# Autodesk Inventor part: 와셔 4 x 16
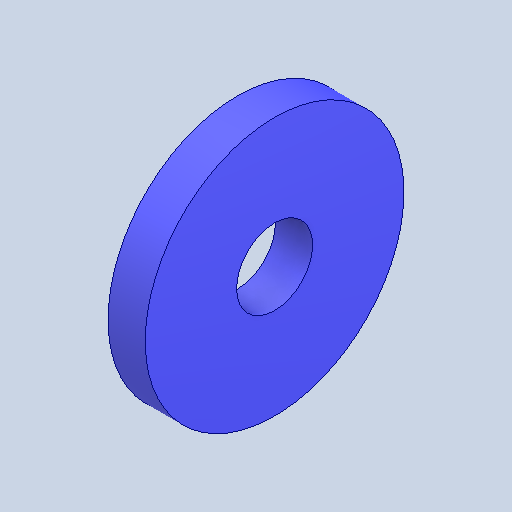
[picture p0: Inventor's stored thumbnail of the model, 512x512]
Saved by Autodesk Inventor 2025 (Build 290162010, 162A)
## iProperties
Created: 2024-07
Part Number: 와셔 4 x 16
Material: 강철, 연강
Description: 미터법 평면 와셔
Document SubType Name: Modeling
Designer: Admin
Density: 7.85 g/cm^3
Appearance: 기본값
Author: jhkim
Sending System: Autodesk Inventor 2025
Preprocessor: ST-DEVELOPER v20
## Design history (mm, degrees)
feature "Solid1"
node "솔리드1"
